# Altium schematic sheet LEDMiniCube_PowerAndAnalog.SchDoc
size A4
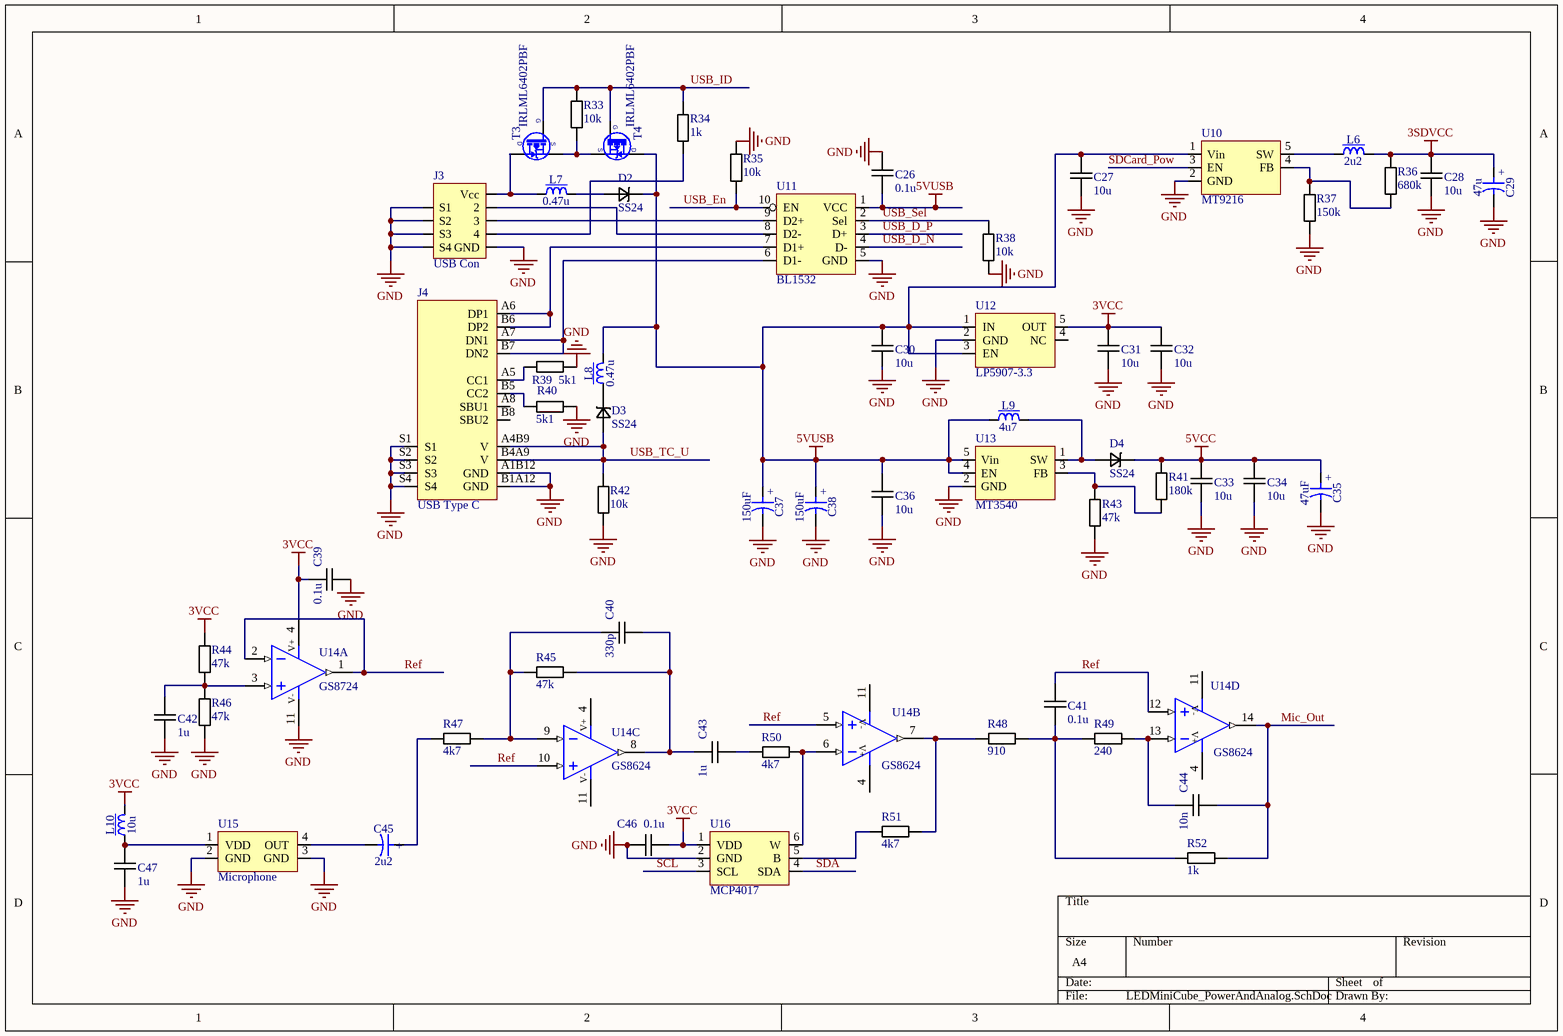
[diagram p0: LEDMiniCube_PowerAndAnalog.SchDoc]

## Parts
C26  0.1u  [CAPC1608L]
C27  10u  [CAPC2012L]
C28  10u  [CAPC2012L]
C29  47u  [CAPMP3216X180N]
C30  10u  [CAPC2012L]
C31  10u  [CAPC2012L]
C32  10u  [CAPC2012L]
C33  10u  [CAPC3216L]
C34  10u  [CAPC3216L]
C35  47uF  [CAPMP3528X120N]
C36  10u  [CAPC2012L]
C37  150uF  [CAPMP7343X200N]
C38  150uF  [CAPMP7343X200N]
C39  0.1u  [CAPC1608L]
C40  330p  [CAPC1608L]
C41  0.1u  [CAPC1608L]
C42  1u  [CAPC1608L]
C43  1u  [CAPC2012L]
C44  10n  [CAPC1608L]
C45  2u2  [CAPMP3216X180N]
C46  0.1u  [CAPC1608L]
C47  1u  [CAPC1608L]
D2  SS24  [SOD-123F]
D3  SS24  [SOD-123F]
D4  SS24  [SOD-123F]
J3  USB Con  [ZX62D]
J4  USB Type C  [U262-161N-4BVC11]
L6  2u2  [IND_COILCRAFT_1206CS]
L7  0.47u  [IND_COILCRAFT_0805CS]
L8  0.47u  [IND_COILCRAFT_0805CS]
L9  4u7  [IND_COILCRAFT_1206CS]
L10  10u  [INDC2012L]
R33  10k  [RESC1608L]
R34  1k  [RESC1608L]
R35  10k  [RESC1608L]
R36  680k  [RESC1608L]
R37  150k  [RESC1608L]
R38  10k  [RESC1608L]
R39  5k1  [RESC1608L]
R40  5k1  [RESC1608L]
R41  180k  [RESC1608L]
R42  10k  [RESC1608L]
R43  47k  [RESC1608L]
R44  47k  [RESC1608L]
R45  47k  [RESC1608L]
R46  47k  [RESC1608L]
R47  4k7  [RESC1608L]
R48  910  [RESC1608L]
R49  240  [RESC1608L]
R50  4k7  [RESC1608L]
R51  4k7  [RESC1608L]
R52  1k  [RESC1608L]
T3  IRLML6402PBF  [SOT95P237X112-3N]
T4  IRLML6402PBF  [SOT95P237X112-3N]
U10  MT9216  [SOT23-5AL]
U11  BL1532  [TSSOP50P490X110-10N]
U12  LP5907-3.3  [SOT95P280X145-5M]
U13  MT3540  [SOT23-5AL]
U14  GS8724  [SOP65P640X120-14N]  (parts A,B,C,D of 4)
U15  Microphone  [Microphone 3.76x2.95]
U16  MCP4017  [SOT65P210X110-6M]

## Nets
3SDVCC: C28.2 C29.1 L6.2 R36.2
3VCC: C31.2 C32.2 C39.1 C46.2 L10.2 R44.2 U12.5(OUT) U14.4(V+) U16.1(VDD)
5VCC: C33.2 C34.2 C35.1 D4.2 R41.2
5VUSB: C26.1 C27.2 C30.2 C36.2 C37.1 C38.1 D2.2 L8.2 L9.1 T4.3(D) U10.1(Vin) U11.1(VCC) U12.1(IN) U12.3(EN) U13.4(EN) U13.5(Vin)
GND: C26.2 C27.1 C28.1 C29.2 C30.1 C31.1 C32.1 C33.1 C34.1 C35.2 C36.1 C37.2 C38.2 C39.2 C42.1 C46.1 C47.1 J3.5(GND) J3.S1 J3.S2 J3.S3 J3.S4 J4.A1B12(GND) J4.B1A12(GND) J4.S1 J4.S2 J4.S3 J4.S4 R35.2 R37.1 R38.1 R39.2 R40.2 R42.1 R43.1 R46.1 U10.2(GND) U11.5(GND) U12.2(GND) U13.2(GND) U14.11(V-) U15.2(GND) U15.3(GND) U16.2(GND)
Mic_Out: C44.2 R52.2 U14.14(OUT)
Ref: C41.2 U14.1(OUT) U14.2(IN-) U14.5(IN+) U14.10(IN+) U14.12(IN+)
SCL: U16.3(SCL)
SDA: U16.4(SDA)
SDCard_Pow: U10.3(EN)
USB_D_N: U11.4(D-)
USB_D_P: U11.3(D+)
USB_En: R35.1 U11.10(EN)
USB_ID: R33.2 R34.2 T3.1(G) T4.1(G)
USB_Sel: R38.2 U11.2(Sel)
USB_TC_U: D3.1 J4.A4B9(V) J4.B4A9(V) R42.2
NetC40_1: C40.1 R45.1 R47.2 U14.9(IN-)
NetC40_2: C40.2 C43.1 R45.2 U14.8(OUT)
NetC41_1: C41.1 R48.2 R49.1 R52.1
NetC42_2: C42.2 R44.1 R46.2 U14.3(IN+)
NetC43_2: C43.2 R50.1
NetC44_1: C44.1 R49.2 U14.13(IN-)
NetC45_1: C45.1 R47.1
NetC45_2: C45.2 U15.4(OUT)
NetC47_2: C47.2 L10.1 U15.1(VDD)
NetD2_1: D2.1 L7.2
NetD3_2: D3.2 L8.1
NetD4_1: D4.1 L9.2 U13.1(SW)
NetJ3_1: J3.1(Vcc) L7.1 T3.3(D)
NetJ3_2: J3.2 U11.8(D2-)
NetJ3_3: J3.3 U11.9(D2+)
NetJ3_4: J3.4 R34.1
NetJ4_A5: J4.A5(CC1) R39.1
NetJ4_A6: J4.A6(DP1) J4.B6(DP2) U11.7(D1+)
NetJ4_A7: J4.A7(DN1) J4.B7(DN2) U11.6(D1-)
NetJ4_B5: J4.B5(CC2) R40.1
NetL6_1: L6.1 U10.5(SW)
NetR33_1: R33.1 T3.2(S) T4.2(S)
NetR36_1: R36.1 R37.2 U10.4(FB)
NetR41_1: R41.1 R43.2 U13.3(FB)
NetR48_1: R48.1 R51.2 U14.7(OUT)
NetR50_2: R50.2 U14.6(IN-) U16.6(W)
NetR51_1: R51.1 U16.5(B)

Not connected (* = marked no-connect by the designer): J4 A8(SBU1) B8(SBU2); U12 4(NC)

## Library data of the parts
C26-C28 C30-C34 C36 C39-C44 C46 C47 = Capacitor
C29 C45 = CTE3216-18_100UF_6.3V_20%_ESR0500_AVX_TLJ: Polarised capacitor; Part Description: ESR 0R5 Solid Tantalum Chip Capacitor; Manufacturer: AVX; Manufacturer Part Number: TLJA107M006R0500; Voltage: 6.3V; Tolerance: ±20%
C35 = CTE3528-12_47UF_10V_20%_PANASONIC_TPG: Polarised capacitor; Voltage: 10V
C37 C38 = CAEM7343-20_150UF_2V_20%_LESR0009: Polarised capacitor; Voltage: 6.3V
D2-D4 = Schotky
J3 = USB
J4 = USB_TypeC
L6 L9 L10 = IND_620NH_5%_COILCRAFT_1206CS: Inductor With Core
L7 L8 = IND_150NH_2%_COILCRAFT_0805CS: Inductor With Core
R33-R52 = Resistor
T3 T4 = IRLML6402PBF: P-CHANNEL MOSFET WITH ZENER DIODE
U10 = LM3671
U12 = TLV70233: Part: LP5907MFX-3.3/NOPB
U13 = TPS6104x
U14 = AD8624ARUZ: Quad Operational Amplifier; Part Number: GS8624-TR
U15 = Microphone MEMS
